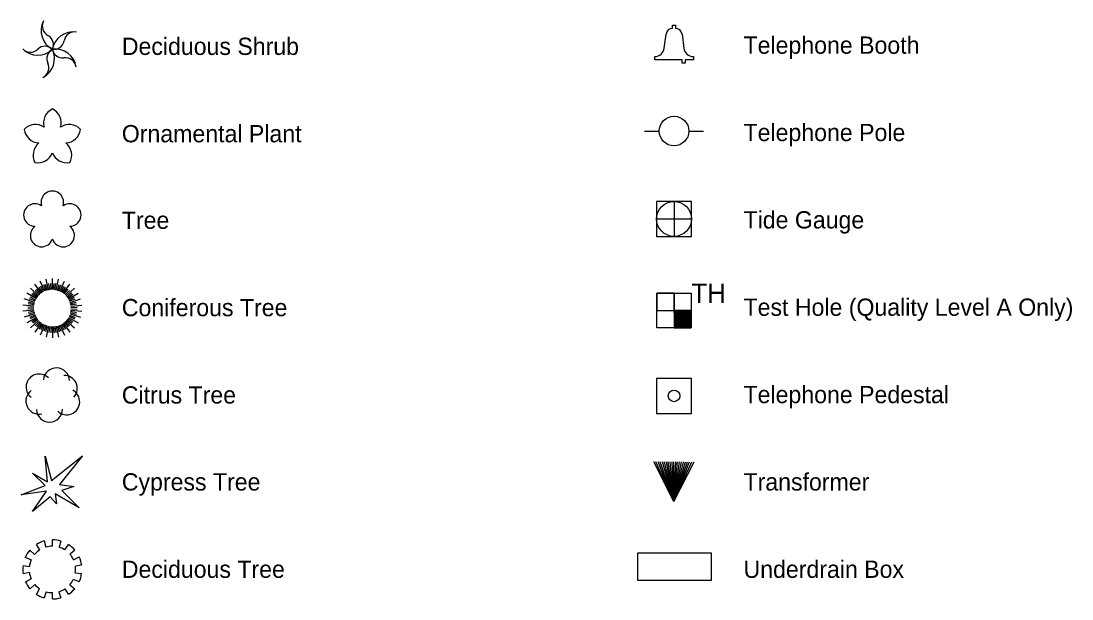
# Model space of a CAD drawing. Extents: x -371 to 730, y -9 to 425.
# Drawn here: x -68.9 to 37.6, y 297.2 to 355.8 of the extents above; entities that cross this region are included whole.
import ezdxf

# ---------------------------------------------------------------- set-up
doc = ezdxf.new("R2010")
doc.units = 0
for name, color, linetype in [('PoleTel_ep', 7, 'Continuous'), ('PowerMisc_ep', 7, 'Continuous'), ('Shrub_ep', 7, 'Continuous'), ('StreamMisc_ep', 7, 'Continuous'), ('SU_TestHole_ep', 7, 'Continuous'), ('TeleMisc_ep', 7, 'Continuous'), ('Tree_ep', 7, 'Continuous'), ('UnderDrain_ep', 7, 'Continuous')]:
    doc.layers.add(name, color=color, linetype=linetype)

msp = doc.modelspace()

# ---------------------------------------------------------------- linework, layer by layer
for centre, radius, start, end in [((-64.7, 354.81), 2.14, 152.7372, 241.9433), ((-65.63, 355.29), 1.1, 152.7372, 241.6186), ((-63.6, 352.55), 2.14, 80.7372, 169.9433), ((-63.44, 353.58), 1.1, 80.7372, 169.6186), ((-66.65, 353.4), 1.05, 333.4027, 61.6186), ((-65.55, 353.96), 1.05, 261.4027, 349.6186), ((-67.19, 354.46), 2.14, 224.7372, 313.9433), ((-67.93, 353.73), 1.1, 224.7372, 313.6186), ((-66.45, 352.18), 1.05, 45.4027, 133.6186), ((-67.63, 351.99), 2.14, 296.7372, 25.9433), ((-65.22, 351.99), 1.05, 117.4027, 205.6186), ((-65.41, 350.81), 2.14, 8.7372, 97.9433), ((-64.67, 353.1), 1.05, 189.4027, 277.6186), ((-67.16, 351.06), 1.1, 296.7372, 25.6186), ((-64.39, 350.97), 1.1, 8.7372, 97.6186)]:
    msp.add_arc(centre, radius, start, end)
at = {"layer": 'PoleTel_ep'}
for p, q in [((-5.72, 344.64), (-4.22, 344.64)), ((-1.22, 344.64), (0.28, 344.64))]:
    msp.add_line(p, q, dxfattribs=at)
msp.add_circle((-2.72, 344.64), 1.5, dxfattribs=at)
at = {"layer": 'PowerMisc_ep'}
for q in [(-4.78, 311.12), (-4.55, 311.12), (-4.32, 311.12), (-4.11, 311.12), (-3.9, 311.12), (-3.7, 311.12), (-3.5, 311.12), (-3.31, 311.12), (-3.11, 311.12), (-2.92, 311.12), (-0.69, 311.12), (-0.92, 311.12), (-1.15, 311.12), (-1.36, 311.12), (-1.57, 311.12), (-1.77, 311.12), (-1.97, 311.12), (-2.16, 311.12), (-2.36, 311.12), (-2.55, 311.12), (-2.73, 311.12)]:
    msp.add_line((-2.73, 307.11), q, dxfattribs=at)
at = {"layer": 'Shrub_ep'}
for centre, start, end in [((-65.03, 345.46), 115.3717, 195.6687), ((-66.38, 345.46), 344.3313, 64.6283), ((-67.42, 343.73), 56.3313, 136.6283), ((-64, 343.73), 43.3717, 123.6687), ((-67, 345.01), 187.3717, 267.6687), ((-64.41, 345.01), 272.3313, 352.6283), ((-66.09, 342.2), 128.3313, 208.6283), ((-65.32, 342.2), 331.3717, 51.6687), ((-67.18, 342.99), 259.3717, 339.6687), ((-64.23, 342.99), 200.3313, 280.6283)]:
    msp.add_arc(centre, 1.57, start, end, dxfattribs=at)
at = {"layer": 'StreamMisc_ep'}
for p, q in [((-2.72, 337.51), (-2.72, 333.97)), ((-4.49, 335.74), (-0.95, 335.74))]:
    msp.add_line(p, q, dxfattribs=at)
msp.add_lwpolyline([(-4.49, 337.51), (-4.49, 333.97), (-0.95, 333.97), (-0.95, 337.51)], close=True, dxfattribs=at)
msp.add_circle((-2.72, 335.74), 1.77, dxfattribs=at)
at = {"layer": 'SU_TestHole_ep'}
for p, q in [((-4.47, 328.2), (-0.97, 328.2)), ((-4.47, 324.7), (-4.47, 328.2)), ((-2.72, 328.2), (-2.72, 324.7)), ((-0.97, 328.2), (-0.97, 324.7)), ((-4.47, 326.45), (-0.97, 326.45)), ((-2.72, 326.45), (-2.72, 326.45)), ((-2.72, 326.43), (-2.7, 326.45)), ((-2.72, 326.41), (-2.69, 326.45)), ((-2.72, 326.4), (-2.67, 326.45)), ((-2.72, 326.38), (-2.65, 326.45)), ((-2.72, 326.37), (-2.64, 326.45)), ((-2.72, 326.35), (-2.62, 326.45)), ((-2.72, 326.33), (-2.6, 326.45)), ((-2.72, 326.32), (-2.59, 326.45)), ((-2.72, 326.3), (-2.57, 326.45)), ((-2.72, 326.28), (-2.56, 326.45)), ((-2.72, 326.27), (-2.54, 326.45)), ((-2.72, 326.25), (-2.52, 326.45)), ((-2.72, 326.24), (-2.51, 326.45)), ((-2.72, 326.22), (-2.49, 326.45)), ((-2.72, 326.2), (-2.47, 326.45)), ((-2.72, 326.19), (-2.46, 326.45)), ((-2.72, 326.17), (-2.44, 326.45)), ((-2.72, 326.15), (-2.43, 326.45)), ((-2.72, 326.14), (-2.41, 326.45)), ((-2.72, 326.12), (-2.39, 326.45)), ((-2.72, 326.11), (-2.38, 326.45)), ((-2.72, 326.09), (-2.36, 326.45)), ((-2.72, 326.07), (-2.35, 326.45)), ((-2.72, 326.06), (-2.33, 326.45)), ((-2.72, 326.04), (-2.31, 326.45)), ((-2.72, 326.02), (-2.3, 326.45)), ((-2.72, 326.01), (-2.28, 326.45)), ((-2.72, 325.99), (-2.26, 326.45)), ((-2.72, 325.98), (-2.25, 326.45)), ((-2.72, 325.96), (-2.23, 326.45)), ((-2.72, 325.94), (-2.22, 326.45)), ((-2.72, 325.93), (-2.2, 326.45)), ((-2.72, 325.91), (-2.18, 326.45)), ((-2.72, 325.89), (-2.17, 326.45)), ((-2.72, 325.88), (-2.15, 326.45)), ((-2.72, 325.86), (-2.13, 326.45)), ((-2.72, 325.85), (-2.12, 326.45)), ((-2.72, 325.83), (-2.1, 326.45)), ((-2.72, 325.81), (-2.09, 326.45)), ((-2.72, 325.8), (-2.07, 326.45)), ((-2.72, 325.78), (-2.05, 326.45)), ((-2.72, 325.76), (-2.04, 326.45)), ((-2.72, 325.75), (-2.02, 326.45)), ((-2.72, 325.73), (-2, 326.45)), ((-2.72, 325.72), (-1.99, 326.45)), ((-2.72, 325.7), (-1.97, 326.45)), ((-2.72, 325.68), (-1.96, 326.45)), ((-2.72, 325.67), (-1.94, 326.45)), ((-2.72, 325.65), (-1.92, 326.45)), ((-2.72, 325.63), (-1.91, 326.45)), ((-2.72, 325.62), (-1.89, 326.45)), ((-2.72, 325.6), (-1.87, 326.45)), ((-2.72, 325.59), (-1.86, 326.45)), ((-2.72, 325.57), (-1.84, 326.45)), ((-2.72, 325.55), (-1.83, 326.45)), ((-2.72, 325.54), (-1.81, 326.45)), ((-2.72, 325.52), (-1.79, 326.45)), ((-2.72, 325.5), (-1.78, 326.45)), ((-2.72, 325.49), (-1.76, 326.45)), ((-2.72, 325.47), (-1.74, 326.45)), ((-2.72, 325.46), (-1.73, 326.45)), ((-2.72, 325.44), (-1.71, 326.45)), ((-2.72, 325.42), (-1.7, 326.45)), ((-2.72, 325.41), (-1.68, 326.45)), ((-2.72, 325.39), (-1.66, 326.45)), ((-2.72, 325.37), (-1.65, 326.45)), ((-2.72, 325.36), (-1.63, 326.45)), ((-2.72, 325.34), (-1.61, 326.45)), ((-2.72, 325.33), (-1.6, 326.45)), ((-2.72, 325.31), (-1.58, 326.45)), ((-2.72, 325.29), (-1.57, 326.45)), ((-2.72, 325.28), (-1.55, 326.45)), ((-2.72, 325.26), (-1.53, 326.45)), ((-2.72, 325.24), (-1.52, 326.45)), ((-2.72, 325.23), (-1.5, 326.45)), ((-2.72, 325.21), (-1.48, 326.45)), ((-2.72, 325.2), (-1.47, 326.45)), ((-2.72, 325.18), (-1.45, 326.45)), ((-2.72, 325.16), (-1.44, 326.45)), ((-2.72, 325.15), (-1.42, 326.45)), ((-2.72, 325.13), (-1.4, 326.45)), ((-2.72, 325.11), (-1.39, 326.45)), ((-2.72, 325.1), (-1.37, 326.45)), ((-2.72, 325.08), (-1.35, 326.45)), ((-2.72, 325.07), (-1.34, 326.45)), ((-2.72, 325.05), (-1.32, 326.45)), ((-2.72, 325.03), (-1.31, 326.45)), ((-2.72, 325.02), (-1.29, 326.45)), ((-2.72, 325), (-1.27, 326.45)), ((-2.72, 324.98), (-1.26, 326.45)), ((-2.72, 324.97), (-1.24, 326.45)), ((-2.72, 324.95), (-1.22, 326.45)), ((-2.72, 324.94), (-1.21, 326.45)), ((-2.72, 324.92), (-1.19, 326.45)), ((-2.72, 324.9), (-1.18, 326.45)), ((-2.72, 324.89), (-1.16, 326.45)), ((-2.72, 324.87), (-1.14, 326.45)), ((-2.72, 324.85), (-1.13, 326.45)), ((-2.72, 324.84), (-1.11, 326.45)), ((-2.72, 324.82), (-1.09, 326.45)), ((-2.72, 324.81), (-1.08, 326.45)), ((-2.72, 324.79), (-1.06, 326.45)), ((-2.72, 324.77), (-1.05, 326.45)), ((-2.72, 324.76), (-1.03, 326.45)), ((-2.72, 324.74), (-1.01, 326.45)), ((-2.72, 324.72), (-1, 326.45)), ((-2.72, 324.71), (-0.98, 326.45)), ((-2.71, 324.7), (-0.97, 326.44)), ((-2.7, 324.7), (-0.97, 326.43)), ((-2.68, 324.7), (-0.97, 326.41)), ((-2.67, 324.7), (-0.97, 326.39)), ((-2.65, 324.7), (-0.97, 326.38)), ((-2.63, 324.7), (-0.97, 326.36)), ((-2.62, 324.7), (-0.97, 326.34)), ((-2.6, 324.7), (-0.97, 326.33)), ((-2.58, 324.7), (-0.97, 326.31)), ((-2.57, 324.7), (-0.97, 326.3)), ((-2.55, 324.7), (-0.97, 326.28)), ((-2.54, 324.7), (-0.97, 326.26)), ((-2.52, 324.7), (-0.97, 326.25)), ((-2.5, 324.7), (-0.97, 326.23)), ((-2.49, 324.7), (-0.97, 326.22)), ((-2.47, 324.7), (-0.97, 326.2)), ((-2.45, 324.7), (-0.97, 326.18)), ((-2.44, 324.7), (-0.97, 326.17)), ((-2.42, 324.7), (-0.97, 326.15)), ((-2.41, 324.7), (-0.97, 326.13)), ((-2.39, 324.7), (-0.97, 326.12)), ((-2.37, 324.7), (-0.97, 326.1)), ((-2.36, 324.7), (-0.97, 326.09)), ((-2.34, 324.7), (-0.97, 326.07)), ((-2.32, 324.7), (-0.97, 326.05)), ((-2.31, 324.7), (-0.97, 326.04)), ((-2.29, 324.7), (-0.97, 326.02)), ((-2.28, 324.7), (-0.97, 326)), ((-2.26, 324.7), (-0.97, 325.99)), ((-2.24, 324.7), (-0.97, 325.97)), ((-2.23, 324.7), (-0.97, 325.96)), ((-2.21, 324.7), (-0.97, 325.94)), ((-2.2, 324.7), (-0.97, 325.92)), ((-2.18, 324.7), (-0.97, 325.91)), ((-2.16, 324.7), (-0.97, 325.89)), ((-2.15, 324.7), (-0.97, 325.87)), ((-2.13, 324.7), (-0.97, 325.86)), ((-2.11, 324.7), (-0.97, 325.84)), ((-2.1, 324.7), (-0.97, 325.83)), ((-2.08, 324.7), (-0.97, 325.81)), ((-2.07, 324.7), (-0.97, 325.79)), ((-2.05, 324.7), (-0.97, 325.78)), ((-2.03, 324.7), (-0.97, 325.76)), ((-2.02, 324.7), (-0.97, 325.74)), ((-2, 324.7), (-0.97, 325.73)), ((-1.98, 324.7), (-0.97, 325.71)), ((-1.97, 324.7), (-0.97, 325.7)), ((-1.95, 324.7), (-0.97, 325.68)), ((-1.94, 324.7), (-0.97, 325.66)), ((-1.92, 324.7), (-0.97, 325.65)), ((-1.9, 324.7), (-0.97, 325.63)), ((-1.89, 324.7), (-0.97, 325.61)), ((-1.87, 324.7), (-0.97, 325.6)), ((-1.85, 324.7), (-0.97, 325.58)), ((-1.84, 324.7), (-0.97, 325.57)), ((-1.82, 324.7), (-0.97, 325.55)), ((-1.81, 324.7), (-0.97, 325.53)), ((-1.79, 324.7), (-0.97, 325.52)), ((-1.77, 324.7), (-0.97, 325.5)), ((-1.76, 324.7), (-0.97, 325.48)), ((-1.74, 324.7), (-0.97, 325.47)), ((-1.72, 324.7), (-0.97, 325.45)), ((-1.71, 324.7), (-0.97, 325.44)), ((-1.69, 324.7), (-0.97, 325.42)), ((-1.68, 324.7), (-0.97, 325.4)), ((-1.66, 324.7), (-0.97, 325.39)), ((-1.64, 324.7), (-0.97, 325.37)), ((-1.63, 324.7), (-0.97, 325.35)), ((-1.61, 324.7), (-0.97, 325.34)), ((-1.59, 324.7), (-0.97, 325.32)), ((-1.58, 324.7), (-0.97, 325.31)), ((-1.56, 324.7), (-0.97, 325.29)), ((-1.55, 324.7), (-0.97, 325.27)), ((-1.53, 324.7), (-0.97, 325.26)), ((-1.51, 324.7), (-0.97, 325.24)), ((-1.5, 324.7), (-0.97, 325.22)), ((-1.48, 324.7), (-0.97, 325.21)), ((-1.46, 324.7), (-0.97, 325.19)), ((-1.45, 324.7), (-0.97, 325.18)), ((-1.43, 324.7), (-0.97, 325.16)), ((-1.42, 324.7), (-0.97, 325.14)), ((-1.4, 324.7), (-0.97, 325.13)), ((-1.38, 324.7), (-0.97, 325.11)), ((-1.37, 324.7), (-0.97, 325.09)), ((-1.35, 324.7), (-0.97, 325.08)), ((-1.33, 324.7), (-0.97, 325.06)), ((-1.32, 324.7), (-0.97, 325.05)), ((-1.3, 324.7), (-0.97, 325.03)), ((-1.29, 324.7), (-0.97, 325.01)), ((-1.27, 324.7), (-0.97, 325)), ((-1.25, 324.7), (-0.97, 324.98)), ((-1.24, 324.7), (-0.97, 324.96)), ((-1.22, 324.7), (-0.97, 324.95)), ((-1.2, 324.7), (-0.97, 324.93)), ((-1.19, 324.7), (-0.97, 324.92)), ((-1.17, 324.7), (-0.97, 324.9)), ((-1.16, 324.7), (-0.97, 324.88)), ((-1.14, 324.7), (-0.97, 324.87)), ((-1.12, 324.7), (-0.97, 324.85)), ((-1.11, 324.7), (-0.97, 324.83)), ((-1.09, 324.7), (-0.97, 324.82)), ((-1.07, 324.7), (-0.97, 324.8)), ((-1.06, 324.7), (-0.97, 324.79)), ((-0.97, 324.7), (-4.47, 324.7)), ((-1.04, 324.7), (-0.97, 324.77)), ((-1.03, 324.7), (-0.97, 324.75)), ((-1.01, 324.7), (-0.97, 324.74)), ((-0.99, 324.7), (-0.97, 324.72)), ((-0.98, 324.7), (-0.97, 324.7))]:
    msp.add_line(p, q, dxfattribs=at)
for points in [[(-4.47, 328.2), (-4.47, 326.45), (-2.72, 326.45), (-2.72, 328.2)], [(-0.97, 324.7), (-0.97, 326.45), (-2.72, 326.45), (-2.72, 324.7)]]:
    msp.add_lwpolyline(points, close=True, dxfattribs=at)
at = {"layer": 'TeleMisc_ep'}
for points in [[(-2.88, 355.37), (-2.56, 355.37), (-2.56, 355.04)], [(-2.88, 355.04), (-2.88, 355.37)], [(-3.71, 353.05), (-3.53, 354.47)], [(-1.91, 354.47), (-1.73, 353.05)], [(-0.76, 352.19), (-0.76, 351.86), (-1.58, 351.86), (-1.58, 351.53), (-1.9, 351.53), (-1.9, 351.86), (-4.68, 351.86), (-4.68, 352.19)]]:
    msp.add_lwpolyline(points, dxfattribs=at)
msp.add_lwpolyline([(-4.49, 319.58), (-4.49, 316.04), (-0.95, 316.04), (-0.95, 319.58)], close=True, dxfattribs=at)
msp.add_circle((-2.72, 317.81), 0.589, dxfattribs=at)
for centre, radius, start, end in [((-2.88, 354.39), 0.653, 90, 172.9818), ((-2.56, 354.39), 0.653, 7.0182, 90), ((-4.68, 353.17), 0.98, 270, 352.9818), ((-0.76, 353.17), 0.98, 187.0182, 270)]:
    msp.add_arc(centre, radius, start, end, dxfattribs=at)
at = {"layer": 'Tree_ep'}
for p, q in [((-66.81, 328.22), (-67.47, 329.13)), ((-66.47, 328.41), (-66.93, 329.44)), ((-66.35, 328.46), (-66.56, 329.05)), ((-66.22, 328.5), (-66.4, 329.1)), ((-66.1, 328.53), (-66.33, 329.64)), ((-65.97, 328.56), (-66.06, 329.18)), ((-65.84, 328.57), (-65.88, 329.19)), ((-65.71, 328.58), (-65.71, 329.7)), ((-65.58, 328.57), (-65.53, 329.19)), ((-65.45, 328.56), (-65.36, 329.18)), ((-65.32, 328.53), (-65.08, 329.64)), ((-65.19, 328.5), (-65.02, 329.1)), ((-65.07, 328.46), (-64.85, 329.05)), ((-64.95, 328.41), (-64.49, 329.44)), ((-64.61, 328.22), (-63.94, 329.13)), ((-67.33, 327.64), (-68.31, 328.2)), ((-67.1, 327.96), (-67.94, 328.71)), ((-67.26, 327.75), (-67.78, 328.1)), ((-67.19, 327.86), (-67.68, 328.24)), ((-67.01, 328.05), (-67.44, 328.5)), ((-66.91, 328.14), (-67.32, 328.62)), ((-66.7, 328.29), (-67.03, 328.82)), ((-66.59, 328.36), (-66.88, 328.91)), ((-64.83, 328.36), (-64.53, 328.91)), ((-64.71, 328.29), (-64.38, 328.82)), ((-64.5, 328.14), (-64.1, 328.62)), ((-64.41, 328.05), (-63.97, 328.5)), ((-64.31, 327.96), (-63.48, 328.71)), ((-64.23, 327.86), (-63.74, 328.24)), ((-64.15, 327.75), (-63.64, 328.1)), ((-64.08, 327.64), (-63.11, 328.2)), ((-67.57, 326.9), (-68.69, 327.01)), ((-67.49, 327.28), (-68.56, 327.63)), ((-67.55, 327.03), (-68.17, 327.13)), ((-67.53, 327.15), (-68.13, 327.31)), ((-67.45, 327.4), (-68.03, 327.64)), ((-67.39, 327.52), (-67.96, 327.8)), ((-64.02, 327.52), (-63.46, 327.8)), ((-63.97, 327.4), (-63.39, 327.64)), ((-63.92, 327.28), (-62.85, 327.63)), ((-63.89, 327.15), (-63.28, 327.31)), ((-63.86, 327.03), (-63.25, 327.13)), ((-63.84, 326.9), (-62.72, 327.01)), ((-67.57, 326.5), (-68.69, 326.39)), ((-67.49, 326.12), (-68.56, 325.77)), ((-67.58, 326.77), (-68.21, 326.79)), ((-67.58, 326.64), (-68.21, 326.61)), ((-67.55, 326.38), (-68.17, 326.27)), ((-67.53, 326.25), (-68.13, 326.1)), ((-67.45, 326), (-68.03, 325.76)), ((-67.39, 325.88), (-67.96, 325.6)), ((-64.02, 325.88), (-63.46, 325.6)), ((-63.97, 326), (-63.39, 325.76)), ((-63.92, 326.12), (-62.85, 325.77)), ((-63.89, 326.25), (-63.28, 326.1)), ((-63.86, 326.38), (-63.25, 326.27)), ((-63.84, 326.5), (-62.72, 326.39)), ((-63.83, 326.77), (-63.21, 326.79)), ((-63.83, 326.64), (-63.21, 326.61)), ((-67.33, 325.76), (-68.31, 325.2)), ((-67.1, 325.45), (-67.94, 324.69)), ((-67.26, 325.65), (-67.78, 325.3)), ((-67.19, 325.55), (-67.68, 325.16)), ((-66.81, 325.18), (-67.47, 324.27)), ((-67.01, 325.35), (-67.44, 324.9)), ((-66.91, 325.26), (-67.32, 324.79)), ((-66.7, 325.11), (-67.03, 324.58)), ((-66.47, 324.99), (-66.93, 323.96)), ((-66.59, 325.05), (-66.88, 324.49)), ((-66.35, 324.94), (-66.56, 324.35)), ((-66.22, 324.9), (-66.4, 324.3)), ((-66.1, 324.87), (-66.33, 323.77)), ((-65.97, 324.84), (-66.06, 324.23)), ((-65.84, 324.83), (-65.88, 324.21)), ((-65.71, 324.83), (-65.71, 323.7)), ((-65.58, 324.83), (-65.53, 324.21)), ((-65.45, 324.84), (-65.36, 324.23)), ((-65.32, 324.87), (-65.08, 323.77)), ((-65.19, 324.9), (-65.02, 324.3)), ((-65.07, 324.94), (-64.85, 324.35)), ((-64.95, 324.99), (-64.49, 323.96)), ((-64.83, 325.05), (-64.53, 324.49)), ((-64.71, 325.11), (-64.38, 324.58)), ((-64.61, 325.18), (-63.94, 324.27)), ((-64.5, 325.26), (-64.1, 324.79)), ((-64.41, 325.35), (-63.97, 324.9)), ((-64.31, 325.45), (-63.48, 324.69)), ((-64.23, 325.55), (-63.74, 325.16)), ((-64.15, 325.65), (-63.64, 325.3)), ((-64.08, 325.76), (-63.11, 325.2)), ((-66.97, 302.22), (-67.32, 302.76)), ((-66.53, 303.12), (-66.37, 302.49)), ((-65.71, 302.58), (-65.69, 303.23)), ((-64.85, 303.1), (-65.02, 302.48)), ((-64.44, 302.21), (-64.08, 302.75)), ((-67.86, 301.19), (-68.45, 301.45)), ((-68, 302.17), (-67.51, 301.74)), ((-63.44, 302.18), (-63.92, 301.76)), ((-63.57, 301.2), (-62.99, 301.49)), ((-68.68, 300.63), (-68.04, 300.53)), ((-62.74, 300.65), (-63.38, 300.54)), ((-68.04, 299.9), (-68.68, 299.78)), ((-68.44, 298.98), (-67.86, 299.27)), ((-62.98, 298.98), (-63.58, 299.22)), ((-63.39, 299.89), (-62.74, 299.8)), ((-67.48, 298.69), (-67.97, 298.26)), ((-67.32, 297.69), (-67, 298.26)), ((-64.08, 297.71), (-64.42, 298.26)), ((-63.94, 298.68), (-63.44, 298.26)), ((-66.34, 297.97), (-66.53, 297.34)), ((-65.71, 297.23), (-65.71, 297.88)), ((-65.06, 297.97), (-64.86, 297.36))]:
    msp.add_line(p, q, dxfattribs=at)
msp.add_lwpolyline([(-62.64, 311.74), (-64.98, 308.84), (-63.55, 308.64), (-64.75, 308.21), (-63, 306.46), (-65.43, 307.88), (-65.28, 306.86), (-65.94, 307.58), (-67.72, 306.1), (-66.29, 308.14), (-68.88, 307.78), (-66.45, 308.74), (-67.72, 309.97), (-66.19, 309.1), (-66.45, 311.69), (-65.78, 309.25)], close=True, dxfattribs=at)
for centre, radius, start, end in [((-65.71, 337.42), 1.14, 343.4738, 196.5262), ((-67.48, 336.13), 1.14, 55.4738, 268.5262), ((-65.71, 335.56), 1.88, 125.4479, 126.5521), ((-65.71, 335.56), 1.88, 53.4479, 54.5521), ((-63.94, 336.13), 1.14, 271.4738, 124.5262), ((-66.8, 334.05), 1.14, 127.4738, 340.5262), ((-65.71, 335.56), 1.88, 197.4479, 198.5521), ((-64.61, 334.05), 1.14, 199.4738, 52.5262), ((-65.71, 335.56), 1.88, 341.4479, 342.5521), ((-65.71, 335.56), 1.88, 269.4479, 270.5521), ((-65.3, 319.32), 1.32, 1.6205, 174.329), ((-67.05, 318.7), 1.32, 44.5604, 231.8956), ((-64.51, 318.56), 1.32, 318.7396, 91.1005), ((-67.07, 317.28), 1.32, 126.5336, 283.4816), ((-64.26, 317.21), 1.32, 226.8204, 62.3168), ((-66, 316.47), 1.32, 181.8244, 358.9316), ((-65.71, 300.23), 3, 105.972, 122.5562), ((-65.71, 300.23), 2.35, 89.9461, 106.3473), ((-65.71, 300.23), 3, 73.2952, 89.5718), ((-65.71, 300.23), 2.35, 57.451, 73.0843), ((-65.71, 300.23), 3, 40.7122, 57.1166), ((-65.71, 300.23), 3, 139.7777, 156.0738), ((-65.71, 300.23), 2.35, 122.254, 140.086), ((-65.71, 300.23), 2.35, 24.4529, 40.4774), ((-65.71, 300.23), 3, 7.9671, 24.8625), ((-65.71, 300.23), 3, 172.27, 188.583), ((-65.71, 300.23), 2.35, 156.0557, 172.7558), ((-65.71, 300.23), 2.35, 351.5431, 7.6203), ((-65.71, 300.23), 2.35, 188.0619, 204.0332), ((-65.71, 300.23), 2.35, 318.6432, 334.5795), ((-65.71, 300.23), 3, 335.3123, 351.7042), ((-65.71, 300.23), 3, 204.5394, 220.9852), ((-65.71, 300.23), 2.35, 221.2062, 236.7795), ((-65.71, 300.23), 2.35, 285.9559, 303.0564), ((-65.71, 300.23), 3, 302.8434, 319.0222), ((-65.71, 300.23), 3, 237.6108, 254.1981), ((-65.71, 300.23), 2.35, 254.31, 270.043), ((-65.71, 300.23), 3, 270.0356, 286.342)]:
    msp.add_arc(centre, radius, start, end, dxfattribs=at)
at = {"layer": 'UnderDrain_ep'}
msp.add_lwpolyline([(-6.43, 299.15), (1.07, 299.15), (1.07, 301.88), (-6.43, 301.88)], close=True, dxfattribs=at)

# ---------------------------------------------------------------- texts
for s, p in [('Deciduous Shrub', (-58.67, 352.35)), ('Telephone Booth', (4.32, 352.47)), ('Ornamental Plant', (-58.67, 343.5)), ('Telephone Pole', (4.32, 343.62)), ('Tide Gauge', (4.32, 334.77)), ('Tree', (-58.67, 334.73)), ('Coniferous Tree', (-58.67, 325.88)), ('Test Hole (Quality Level A Only)', (4.32, 325.92)), ('Citrus Tree', (-58.67, 317.03)), ('Telephone Pedestal', (4.32, 317.07)), ('Cypress Tree', (-58.67, 308.22)), ('Transformer', (4.32, 308.22)), ('Deciduous Tree', (-58.67, 299.37)), ('Underdrain Box', (4.32, 299.37))]:
    msp.add_text(s, height=1.75).set_placement(p)
at = {"layer": 'SU_TestHole_ep'}
msp.add_text('TH', height=1.96, dxfattribs=at).set_placement((-0.97, 327.22))

doc.saveas('drawing.dxf')
